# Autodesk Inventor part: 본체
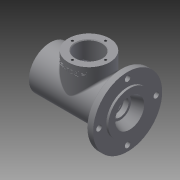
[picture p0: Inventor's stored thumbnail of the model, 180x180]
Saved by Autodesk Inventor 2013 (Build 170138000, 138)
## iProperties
Created: 2016-08
Part Number: 본체
Material: 일반
Document SubType Name: Modeling
Designer: Administrator
Density: 1 g/cm^3
Author: Administrator
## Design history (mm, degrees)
sketch "스케치1"
  geometry: C1 r 31 at (0, 0); C2 r 26 at (0, 0); 1 further point
  constraints: 2 centre point, 2 coincident
  dimensions: "d8" = 62 diameter of C1; "d9" = 52 diameter of C2
extrude "돌출1" new body sketch "스케치1" stored distance "d10" = 115; taper "d11" = 0 deg
sketch "스케치2"
  geometry: L1 (-57.5, -31)-(-57.5, 31) reference; L2 (-57.5, 31)-(57.5, 31) reference; L3 (57.5, 31)-(57.5, -31) reference; L4 (57.5, -31)-(-57.5, -31) reference; L5 (0, 0)-(57.5, 0); L6 (44.5, 31)-(54.5, 31); L7 (54.5, 31)-(54.5, 50); L8 (54.5, 50)-(44.5, 50); L9 (44.5, 50)-(44.5, 31)
  constraints: 10 end point, 2 parallel, 1 horizontal, 1 midpoint, 1 perpendicular, 1 point on line
  dimensions: "d12" = 3 distance between parallel lines of L3 L7; "d13" = 13 distance between parallel lines of L3 L9; "d14" = 100 diameter of L8 L5
revolve "회전1" sketch "스케치2" stored, may be unused: angle "d15" = 90 deg
node "작업 평면1"
sketch "스케치4"
  geometry: L1 (44.5, 31)-(44.5, -31) reference; L2 (-57.5, 31)-(-57.5, -31) reference; L3 (-57.5, 0)-(0, 0); C1 r 30 at (-1.5, 0)
  constraints: 2 end point, 1 centre point, 1 midpoint, 1 perpendicular, 1 point on line
  dimensions: "d47" = 60 diameter of C1; "d48" = 56 distance from line of L2 C1.centre
extrude "돌출3" join sketch "스케치4" stored distance "d49" = 0; taper "d50" = 0 deg
sketch "스케치5" dims "d60" = 48
  geometry: L1 (0, 0)-(0, 24); C1 r 30 at (0, 0) reference; 2 further points
  constraints: 2 coincident, 2 end point, 1 vertical, 1 vertical alignment, 2 other
hole "구멍2" sketch "스케치5" at (0, 24) diameter "d61" = 3.459; stored, may be unused: countersink angle "d65" = 90 deg, drill point angle "d67" = 118 deg; dims "d62" = 8, "d63" = 4, "d64" = 2, "d66" = 10
sketch "스케치7" dims "d80" = 83
  geometry: L1 (0, 0)-(0, 41.5); 2 further points
  constraints: 2 coincident, 2 end point, 1 vertical, 1 vertical alignment, 2 other
hole "구멍3" sketch "스케치7" at (0, 41.5) diameter "d81" = 8; stored, may be unused: countersink angle "d85" = 90 deg, drill point angle "d87" = 118 deg; dims "d82" = 8, "d83" = 4, "d84" = 2, "d86" = 10
node "작업 평면2"
sketch "스케치8" dims "d95" = 3
  geometry: L1 (-21.122, -6.998)-(21.122, -6.998); L2 (21.122, -6.998)-(21.122, -13.002); L3 (21.122, -13.002)-(-21.122, -13.002); L4 (-21.122, -13.002)-(-21.122, -6.998); L5 (-21.122, -10)-(21.122, -10); L6 (0, -13.002)-(0, -6.998); L7 (-30, 0)-(30, 0) reference; L8 (-56, -18)-(-56, -80) reference; 1 further point
  constraints: 4 end point, 4 midpoint, 2 other
  dimensions: "d91" = 10 distance between parallel lines of L5 L7; "d92" = 56 distance between parallel lines of L8 L6
feature "엠보싱1" sketch "스케치8" dims "d93" = 0.5, "d94" = 0
fillet "모깎기1" dims "d95" = 3
sketch "스케치10"
  geometry: L1 (-44.5, 47)-(-44.5, 45.5) reference; L2 (-44.5, 45.5)-(-54.5, 45.5) reference; L3 (-54.5, 45.5)-(-54.5, 50) reference; L4 (-54.5, 50)-(-47.5, 50) reference; L5 (-47.5, -50)-(-54.5, -50) reference; L6 (-54.5, -50)-(-54.5, -45.5) reference; L7 (-54.5, -45.5)-(-44.5, -45.5) reference; L8 (-44.5, -45.5)-(-44.5, -47) reference; L9 (-24.23, 39)-(-22.5, 37.961) reference; L10 (-22.5, 37.961)-(-20.771, 39) reference; L11 (-20.771, 39)-(-20.771, 49) reference; L12 (-20.771, 49)-(23.77, 49) reference; L13 (23.77, 49)-(23.77, 39) reference; L14 (23.77, 39)-(25.5, 37.961) reference; L15 (25.5, 37.961)-(27.23, 39) reference; L16 (27.23, 39)-(27.23, 49) reference; L17 (27.23, 49)-(31.5, 49) reference; L18 (31.5, 49)-(31.5, 34) reference; L19 (34.5, 31)-(57.5, 31) reference; L20 (57.5, 31)-(57.5, -31) reference; L21 (57.5, -31)-(-41.5, -31) reference; L22 (-44.5, -34)-(-44.5, -37.5) reference; L23 (-44.5, -37.5)-(-54.5, -37.5) reference; L24 (-54.5, -37.5)-(-54.5, -31) reference; L25 (-54.5, -31)-(-57.5, -31) reference; L26 (-57.5, -31)-(-57.5, 31) reference; L27 (-57.5, 31)-(-54.5, 31) reference; L28 (-54.5, 31)-(-54.5, 37.5) reference; L29 (-54.5, 37.5)-(-44.5, 37.5) reference; L30 (-44.5, 37.5)-(-44.5, 34) reference; L31 (-41.5, 31)-(-31.5, 31) reference; L32 (-28.5, 34)-(-28.5, 49) reference; L33 (-28.5, 49)-(-24.23, 49) reference; L34 (-24.23, 49)-(-24.23, 39) reference; L35 (-44.5, 47)-(-44.5, 45.5) reference; L36 (-44.5, 45.5)-(-54.5, 45.5) reference; L37 (-54.5, 45.5)-(-54.5, 50) reference; L38 (-54.5, 50)-(-47.5, 50) reference; L39 (-47.5, -50)-(-54.5, -50) reference; L40 (-54.5, -50)-(-54.5, -45.5) reference; L41 (-54.5, -45.5)-(-44.5, -45.5) reference; L42 (-44.5, -45.5)-(-44.5, -47) reference; L43 (-24.23, 39)-(-22.5, 37.961) reference; L44 (-22.5, 37.961)-(-20.771, 39) reference; L45 (-20.771, 39)-(-20.771, 49) reference; L46 (-20.771, 49)-(23.77, 49) reference; L47 (23.77, 49)-(23.77, 39) reference; L48 (23.77, 39)-(25.5, 37.961) reference; L49 (25.5, 37.961)-(27.23, 39) reference; L50 (27.23, 39)-(27.23, 49) reference; L51 (27.23, 49)-(31.5, 49) reference; L52 (31.5, 49)-(31.5, 34) reference; L53 (34.5, 31)-(57.5, 31) reference; L54 (57.5, 31)-(57.5, -31) reference; L55 (57.5, -31)-(-41.5, -31) reference; L56 (-44.5, -34)-(-44.5, -37.5) reference; L57 (-44.5, -37.5)-(-54.5, -37.5) reference; L58 (-54.5, -37.5)-(-54.5, -31) reference; L59 (-54.5, -31)-(-57.5, -31) reference; L60 (-57.5, -31)-(-57.5, 31) reference; L61 (-57.5, 31)-(-54.5, 31) reference; L62 (-54.5, 31)-(-54.5, 37.5) reference; L63 (-54.5, 37.5)-(-44.5, 37.5) reference; L64 (-44.5, 37.5)-(-44.5, 34) reference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; A1 r 3 centre (-47.5, 47) between (-44.5, 47) and (-47.5, 50) reference; A2 r 3 centre (-47.5, -47) between (-47.5, -50) and (-44.5, -47) reference; A3 r 3 centre (-41.5, -34) between (-41.5, -31) and (-44.5, -34) reference; A4 r 3 centre (-41.5, 34) between (-44.5, 34) and (-41.5, 31) reference; A5 r 3 centre (-47.5, 47) between (-44.5, 47) and (-47.5, 50) reference; A6 r 3 centre (-47.5, -47) between (-47.5, -50) and (-44.5, -47) reference; A7 r 3 centre (-41.5, -34) between (-41.5, -31) and (-44.5, -34) reference; A8 r 3 centre (-41.5, 34) between (-44.5, 34) and (-41.5, 31) reference; A9 r 3 centre (17.5, 23) between (20.5, 23) and (17.5, 26); A10 r 3 centre (-14.5, 23) between (-14.5, 26) and (-17.5, 23); A11 r 3 centre (-30.5, 13.5) between (-30.5, 16.5) and (-33.5, 13.5); A12 r 0.3 centre (36.8, 19.7) between (36.8, 20) and (36.5, 19.7); A13 r 0.3 centre (-36.5, 12.2) between (-36.2, 12.2) and (-36.5, 12.5); A14 r 3 centre (-46.5, 13.886) between (-43.5, 13.886) and (-45.491, 16.711); 6 further points
  constraints: 112 end point, 27 point on line, 26 parallel, 12 perpendicular, 12 point on circle, 12 tangent, 11 horizontal, 6 centre point, 4 equal radius, 3 collinear, 3 midpoint, 5 other
  dimensions: "d105" = 56 distance between parallel lines of L20 L69; "d106" = 12 distance between parallel lines of L20 L76; "d107" = 42 diameter of L73 L70; "d108" = 3 distance of L76.end L77.end; "d109" = 48 diameter of L77 L70; "d110" = 40 diameter of L81 L70; "d111" = 35 diameter of L85 L70; "d112" = 37 diameter of L89 L70; "d113" = 1.75 distance of L88.end L89.end; "d114" = 21 distance between parallel lines of L20 L86; "d116" = 38 distance between parallel lines of L92 L100; "d117" = 26 distance between parallel lines of L20 L84; "d118" = 35 diameter of L97 L70; "d119" = 5 distance of L101.start point (-33.5, 16.5); "d120" = 14 distance between parallel lines of L26 L110; "d121" = 32 diameter of point (-43.5, 16) L70; "d122" = 42 diameter of L95.start L70; "d123" = 86 distance between parallel lines of L20 L98; "d124" = 20 diameter of L107 L70; "d125" = 2.7 distance of L106.end L107.end; "d126" = 25 diameter of L111 L70; "d127" = 33 diameter of L101 L70; "d128" = 52 diameter of L115 L113; "d129" = 38 distance of point (-17.5, 26) point (20.5, 26); "d130" = 3 radius of A9; "d131" = 0.3 radius of A12; "d132" = 1 distance of L97.start L118.start; "d133" = 1 distance of L114.start L118.start (= d132); "d134" = 1 distance of L111.start L122.start; "d135" = 1 distance of L96.end L122.start (= d134); "d136" = 1 distance of L93.start L121.start; "d137" = 1 distance of L116.end L121.start (= d136)
  node "절단 모서리 투영4"
  node "절단 모서리 투영5"
revolve "회전4" stored, may be unused: angle "d138" = 90 deg
revolve "회전5" stored, may be unused: angle "d139" = 90 deg
revolve "회전6" stored, may be unused: angle "d140" = 90 deg
sketch "스케치11"
  geometry: L1 (-44.5, 47)-(-44.5, 45.5) reference; L2 (-44.5, 45.5)-(-54.5, 45.5) reference; L3 (-54.5, 45.5)-(-54.5, 50) reference; L4 (-54.5, 50)-(-47.5, 50) reference; L5 (-47.5, -50)-(-54.5, -50) reference; L6 (-54.5, -50)-(-54.5, -45.5) reference; L7 (-54.5, -45.5)-(-44.5, -45.5) reference; L8 (-44.5, -45.5)-(-44.5, -47) reference; L9 (-24.23, 39)-(-22.5, 37.961) reference; L10 (-22.5, 37.961)-(-20.771, 39) reference; L11 (-20.771, 39)-(-20.771, 49) reference; L12 (-20.771, 49)-(23.77, 49) reference; L13 (23.77, 49)-(23.77, 39) reference; L14 (23.77, 39)-(25.5, 37.961) reference; L15 (25.5, 37.961)-(27.23, 39) reference; L16 (27.23, 39)-(27.23, 49) reference; L17 (27.23, 49)-(31.5, 49) reference; L18 (31.5, 49)-(31.5, 34) reference; L19 (34.5, 31)-(57.5, 31) reference; L20 (57.5, 31)-(57.5, 21) reference; L21 (57.5, 21)-(48.5, 21) reference; L22 (48.5, 21)-(48.5, 24) reference; L23 (48.5, 24)-(45.5, 24) reference; L24 (45.5, 24)-(45.5, 20) reference; L25 (45.5, 20)-(36.8, 20) reference; L26 (36.5, 19.7)-(36.5, 17.5) reference; L27 (36.5, 17.5)-(31.5, 17.5) reference; L28 (31.5, 17.5)-(31.5, 18.5) reference; L29 (31.5, 18.5)-(29.75, 18.5) reference; L30 (29.75, 18.5)-(29.75, 17.5) reference; L31 (29.75, 17.5)-(21.5, 17.5) reference; L32 (21.5, 17.5)-(20.5, 18.5) reference; L33 (20.5, 18.5)-(20.5, 23) reference; L34 (17.5, 26)-(-14.5, 26) reference; L35 (-17.5, 23)-(-17.5, 18.5) reference; L36 (-17.5, 18.5)-(-18.5, 17.5) reference; L37 (-18.5, 17.5)-(-28.5, 17.5) reference; L38 (-28.5, 17.5)-(-28.5, -17.5) reference; L39 (-28.5, -17.5)-(-18.5, -17.5) reference; L40 (-18.5, -17.5)-(-17.5, -18.5) reference; L41 (-17.5, -18.5)-(-17.5, -23) reference; L42 (-14.5, -26)-(17.5, -26) reference; L43 (20.5, -23)-(20.5, -18.5) reference; L44 (20.5, -18.5)-(21.5, -17.5) reference; L45 (21.5, -17.5)-(29.75, -17.5) reference; L46 (29.75, -17.5)-(29.75, -18.5) reference; L47 (29.75, -18.5)-(31.5, -18.5) reference; L48 (31.5, -18.5)-(31.5, -17.5) reference; L49 (31.5, -17.5)-(36.5, -17.5) reference; L50 (36.5, -17.5)-(36.5, -19.7) reference; L51 (36.8, -20)-(45.5, -20) reference; L52 (45.5, -20)-(45.5, -24) reference; L53 (45.5, -24)-(48.5, -24) reference; L54 (48.5, -24)-(48.5, -21) reference; L55 (48.5, -21)-(57.5, -21) reference; L56 (57.5, -21)-(57.5, -31) reference; L57 (57.5, -31)-(-41.5, -31) reference; L58 (-44.5, -34)-(-44.5, -37.5) reference; L59 (-44.5, -37.5)-(-54.5, -37.5) reference; L60 (-54.5, -37.5)-(-54.5, -31) reference; L61 (-54.5, -31)-(-57.5, -31) reference; L62 (-57.5, -31)-(-57.5, 31) reference; L63 (-57.5, 31)-(-54.5, 31) reference; L64 (-54.5, 31)-(-54.5, 37.5) reference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; A1 r 3 centre (-47.5, 47) between (-44.5, 47) and (-47.5, 50) reference; A2 r 3 centre (-47.5, -47) between (-47.5, -50) and (-44.5, -47) reference; A3 r 0.3 centre (36.8, 19.7) between (36.8, 20) and (36.5, 19.7) reference; A4 r 3 centre (17.5, 23) between (20.5, 23) and (17.5, 26) reference; A5 r 3 centre (-14.5, 23) between (-14.5, 26) and (-17.5, 23) reference; A6 r 3 centre (-14.5, -23) between (-17.5, -23) and (-14.5, -26) reference; A7 r 3 centre (17.5, -23) between (17.5, -26) and (20.5, -23) reference; A8 r 0.3 centre (36.8, -19.7) between (36.5, -19.7) and (36.8, -20) reference; A9 r 3 centre (-41.5, -34) between (-41.5, -31) and (-44.5, -34) reference; A10 r 3 centre (-41.5, 34) between (-44.5, 34) and (-41.5, 31) reference; A11 r 3 centre (-30.5, 13.5) between (-30.5, 16.5) and (-33.5, 13.5); A12 r 0.3 centre (-36.5, 12.2) between (-36.2, 12.2) and (-36.5, 12.5); 1 further point
  constraints: 30 end point, 6 parallel, 4 perpendicular, 4 point on circle, 4 point on line, 4 tangent, 3 horizontal, 2 centre point, 1 collinear, 1 midpoint, 2 other
  dimensions: "d141" = 32 diameter of L72.end L71; "d143" = 42 diameter of L72.start L71; "d144" = 14 distance between parallel lines of L62 L73; "d145" = 33 diameter of L82 L71; "d146" = 2.7 distance of L79.end L80.end; "d147" = 25 diameter of L76 L71; "d148" = 7.3 distance of point (-36.2, 12.5) L76.end; "d149" = 20 diameter of L80 L71; "d150" = 3 radius of A11; "d151" = 0.3 radius of A12
revolve "회전7" sketch "스케치11" stored, may be unused: angle "d152" = 90 deg
hole "구멍4" diameter "d155" = 38; stored, may be unused: countersink angle "d159" = 90 deg, drill point angle "d161" = 118 deg; dims "d153" = 10, "d154" = 10, "d156" = 8, "d157" = 4, "d158" = 2, "d160" = 10
feature "스레드2" dims "d162" = 10, "d163" = 0
chamfer "모따기2" distance "d164" = 1; stored, may be unused: second distance "d165" = 2, angle "d166" = 45 deg
node "솔리드1"
pattern_circular "원형 패턴1" dims angle "d69" = 360 deg
pattern_circular "원형 패턴2" dims angle "d89" = 360 deg
node "투영된 루프1"
node "투영된 루프2"
node "절단 모서리 투영1"
node "절단 모서리 투영6"
other parameters: "d46" = 49
